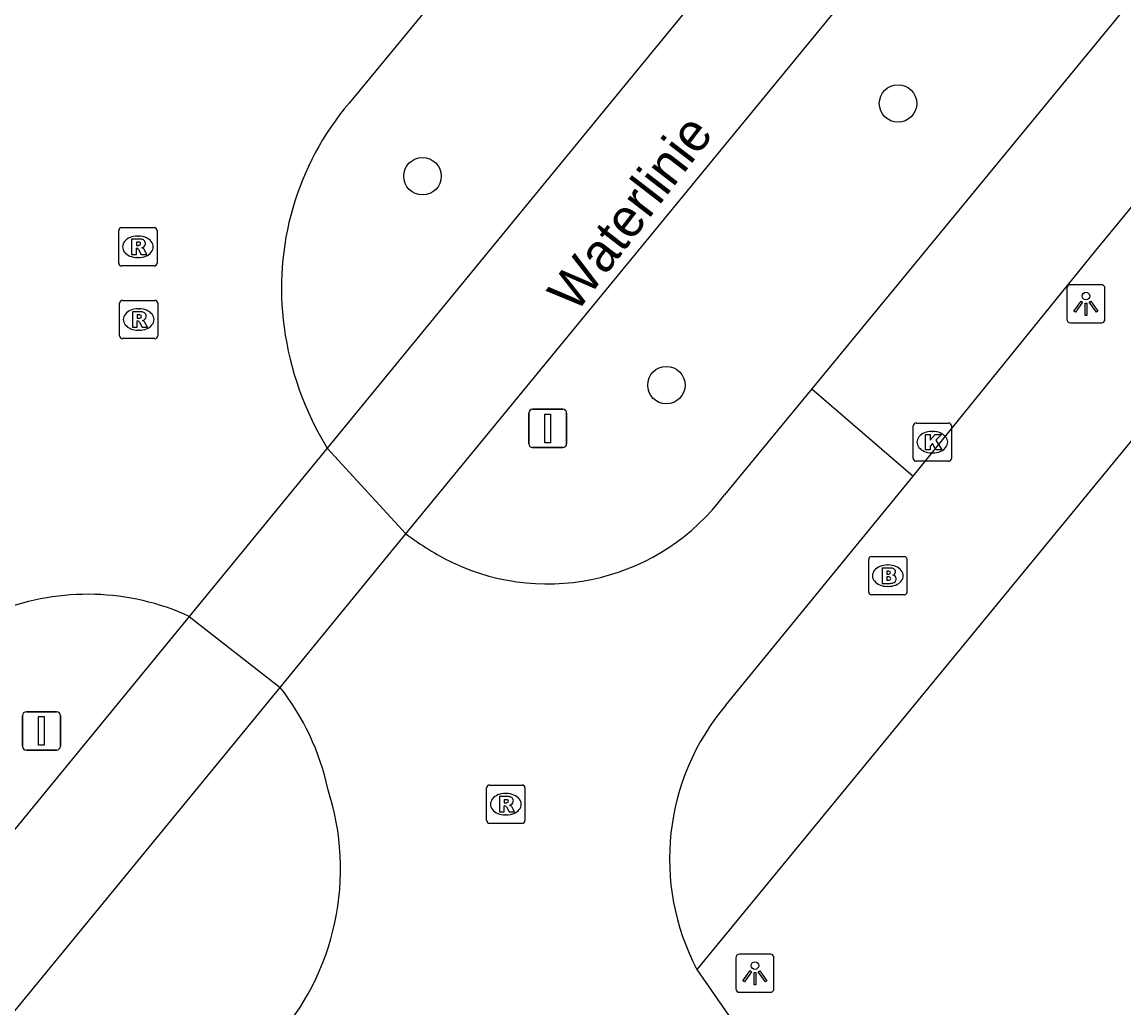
# Model space of a CAD drawing. Extents: x 155275 to 156263, y 382654 to 383635.
# Drawn here: x 155568.42 to 155597.21, y 382967.18 to 382992.94 of the extents above; entities that cross this region are included whole.
import ezdxf

# ---------------------------------------------------------------- set-up
doc = ezdxf.new("R2010")
doc.units = 0
for name, color, linetype in [('IMGEO_Boom', 7, 'Continuous'), ('IMGEO_Brandkraan', 7, 'Continuous'), ('IMGEO_Fietspad_gesloten', 7, 'Continuous'), ('IMGEO_Kolk', 7, 'Continuous'), ('IMGEO_Lichtpunt', 7, 'Continuous'), ('IMGEO_Openbare_ruimte_label', 7, 'Continuous'), ('IMGEO_Rijbaan_lokaal_gesloten', 7, 'Continuous'), ('IMGEO_Rijbaan_lokaal_open', 7, 'Continuous'), ('IMGEO_Rioolput', 7, 'Continuous'), ('IMGEO_Verkeersbordpaal', 7, 'Continuous'), ('IMGEO_Voetpad_open', 7, 'Continuous')]:
    doc.layers.add(name, color=color, linetype=linetype)

msp = doc.modelspace()

# ---------------------------------------------------------------- linework, layer by layer
at = {"layer": 'IMGEO_Boom'}
for centre in [(155591.307, 382990.81), (155578.883, 382988.909), (155585.255, 382983.451)]:
    msp.add_circle(centre, 0.489, dxfattribs=at)
at = {"layer": 'IMGEO_Brandkraan'}
for p, q in [((155590.54, 382978.046), (155590.54, 382978.898)), ((155590.615, 382978.972), (155591.467, 382978.972)), ((155591.028, 382978.752), (155591.053, 382978.752)), ((155591.541, 382978.898), (155591.541, 382978.046)), ((155591.051, 382978.192), (155591.026, 382978.192)), ((155591.467, 382977.972), (155590.615, 382977.972))]:
    msp.add_line(p, q, dxfattribs=at)
for points in [[(155590.54, 382978.046), (155590.54, 382978.898)], [(155590.615, 382978.972), (155591.467, 382978.972)], [(155591.541, 382978.898), (155591.541, 382978.046)], [(155590.888, 382978.672), (155590.888, 382978.272), (155591.101, 382978.272)], [(155591.119, 382978.672), (155590.888, 382978.672)], [(155591.067, 382978.591), (155591.013, 382978.591), (155591.013, 382978.515)], [(155591.013, 382978.515), (155591.066, 382978.515)], [(155591.075, 382978.439), (155591.013, 382978.439), (155591.013, 382978.358)], [(155591.013, 382978.358), (155591.075, 382978.358)], [(155591.467, 382977.972), (155590.615, 382977.972)]]:
    msp.add_lwpolyline(points, dxfattribs=at)
for centre, radius, start, end in [((155590.617, 382978.896), 0.0765, 91.552, 178.448), ((155590.617, 382978.896), 0.0765, 91.552, 178.448), ((155591.465, 382978.896), 0.0765, 1.552, 88.448), ((155591.465, 382978.896), 0.0765, 1.552, 88.448), ((155591.068, 382978.553), 0.0379, 267.8285, 90.9355), ((155591.076, 382978.398), 0.0404, 269.8759, 90.5077), ((155591.123, 382978.527), 0.145, 59.4692, 91.5367), ((155591.148, 382978.574), 0.0922, 285.5137, 58.1501), ((155591.153, 382978.382), 0.105, 301.3115, 78.989), ((155591.107, 382978.523), 0.251, 268.6676, 293.5347), ((155590.617, 382978.048), 0.0765, 181.552, 268.448), ((155590.617, 382978.048), 0.0765, 181.552, 268.448), ((155591.465, 382978.048), 0.0765, 271.552, 358.448), ((155591.465, 382978.048), 0.0765, 271.552, 358.448)]:
    msp.add_arc(centre, radius, start, end, dxfattribs=at)
for centre, major_axis, ratio, start_param, end_param in [((155591.027, 382978.472), (-0.387, 0.002), 0.722429, 4.712389, 7.853982), ((155591.052, 382978.472), (-0.39, 0.002), 0.717154, 1.570796, 4.712389)]:
    msp.add_ellipse(centre, major_axis=major_axis, ratio=ratio, start_param=start_param, end_param=end_param, dxfattribs=at)
at = {"layer": 'IMGEO_Fietspad_gesloten'}
for points in [[(155706.581, 383139.306), (155702.643, 383134.878), (155693.747, 383124.076), (155661.118, 383084.828), (155644.459, 383064.506), (155599.926, 383010.505), (155576.394, 382981.806)], [(155578.449, 382979.563), (155602.123, 383008.412), (155669.504, 383090.181), (155696.136, 383122.234), (155702.244, 383129.715), (155705.062, 383133.055), (155708.331, 383136.749)], [(155578.449, 382979.563), (155576.394, 382981.806)], [(155572.789, 382977.41), (155548.966, 382948.356), (155528.673, 382923.729), (155507.607, 382898.405), (155494.374, 382882.291)], [(155572.789, 382977.41), (155575.161, 382975.555)], [(155496.67, 382880.437), (155497.335, 382881.332), (155511.334, 382898.215), (155518.802, 382907.088), (155545.301, 382939.168), (155575.161, 382975.555)]]:
    msp.add_lwpolyline(points, dxfattribs=at)
at = {"layer": 'IMGEO_Kolk'}
for p, q in [((155591.777, 382982.461), (155592.629, 382982.461)), ((155591.702, 382981.535), (155591.702, 382982.387)), ((155592.19, 382982.241), (155592.215, 382982.241)), ((155592.703, 382982.387), (155592.703, 382981.535)), ((155592.213, 382981.681), (155592.188, 382981.681)), ((155592.629, 382981.461), (155591.777, 382981.461))]:
    msp.add_line(p, q, dxfattribs=at)
for points in [[(155591.777, 382982.461), (155592.629, 382982.461)], [(155591.702, 382981.535), (155591.702, 382982.387)], [(155592.023, 382982.161), (155592.146, 382982.161), (155592.146, 382982.01), (155592.276, 382982.161), (155592.44, 382982.161), (155592.294, 382982.01), (155592.447, 382981.761), (155592.295, 382981.761), (155592.21, 382981.925), (155592.146, 382981.858), (155592.146, 382981.761), (155592.023, 382981.761), (155592.023, 382982.161)], [(155592.703, 382982.387), (155592.703, 382981.535)], [(155592.629, 382981.461), (155591.777, 382981.461)]]:
    msp.add_lwpolyline(points, dxfattribs=at)
for centre, start, end in [((155591.779, 382982.385), 91.552, 178.448), ((155591.779, 382982.385), 91.552, 178.448), ((155592.627, 382982.385), 1.552, 88.448), ((155592.627, 382982.385), 1.552, 88.448), ((155591.779, 382981.537), 181.552, 268.448), ((155591.779, 382981.537), 181.552, 268.448), ((155592.627, 382981.537), 271.552, 358.448), ((155592.627, 382981.537), 271.552, 358.448)]:
    msp.add_arc(centre, 0.0765, start, end, dxfattribs=at)
for centre, major_axis, ratio, start_param, end_param in [((155592.189, 382981.961), (-0.387, 0.002), 0.722429, 4.712389, 7.853982), ((155592.214, 382981.961), (-0.39, 0.002), 0.717154, 1.570796, 4.712389)]:
    msp.add_ellipse(centre, major_axis=major_axis, ratio=ratio, start_param=start_param, end_param=end_param, dxfattribs=at)
at = {"layer": 'IMGEO_Lichtpunt'}
for p, q in [((155595.717, 382985.98), (155595.717, 382985.173)), ((155595.717, 382985.98), (155595.717, 382985.173)), ((155596.619, 382986.075), (155595.811, 382986.075)), ((155596.619, 382986.075), (155595.811, 382986.075)), ((155596.713, 382985.173), (155596.713, 382985.98)), ((155596.713, 382985.173), (155596.713, 382985.98)), ((155595.811, 382985.079), (155596.619, 382985.079)), ((155595.811, 382985.079), (155596.619, 382985.079)), ((155587.069, 382968.489), (155587.069, 382967.682)), ((155587.069, 382968.489), (155587.069, 382967.682)), ((155587.971, 382968.584), (155587.163, 382968.584)), ((155587.971, 382968.584), (155587.163, 382968.584)), ((155588.065, 382967.682), (155588.065, 382968.489)), ((155588.065, 382967.682), (155588.065, 382968.489)), ((155587.163, 382967.588), (155587.971, 382967.588)), ((155587.163, 382967.588), (155587.971, 382967.588))]:
    msp.add_line(p, q, dxfattribs=at)
for points in [[(155596.091, 382985.644), (155596.13, 382985.616), (155595.942, 382985.354), (155595.904, 382985.381), (155596.091, 382985.644)], [(155596.303, 382985.616), (155596.341, 382985.643), (155596.528, 382985.381), (155596.489, 382985.353), (155596.303, 382985.616)], [(155596.193, 382985.596), (155596.24, 382985.596), (155596.24, 382985.274), (155596.193, 382985.274), (155596.193, 382985.596)], [(155587.443, 382968.153), (155587.482, 382968.125), (155587.294, 382967.863), (155587.256, 382967.89), (155587.443, 382968.153)], [(155587.545, 382968.105), (155587.592, 382968.105), (155587.592, 382967.783), (155587.545, 382967.783), (155587.545, 382968.105)], [(155587.655, 382968.125), (155587.693, 382968.152), (155587.88, 382967.89), (155587.841, 382967.862), (155587.655, 382968.125)]]:
    msp.add_lwpolyline(points, dxfattribs=at)
for centre in [(155596.216, 382985.778), (155587.568, 382968.287)]:
    msp.add_circle(centre, 0.0994, dxfattribs=at)
for centre, start, end in [((155595.811, 382985.98), 90, 180), ((155595.811, 382985.98), 90, 180), ((155596.619, 382985.98), 0, 90), ((155596.619, 382985.98), 0, 90), ((155595.811, 382985.173), 180, 270), ((155595.811, 382985.173), 180, 270), ((155596.619, 382985.173), 270, 0), ((155596.619, 382985.173), 270, 360), ((155587.163, 382968.489), 90, 180), ((155587.163, 382968.489), 90, 180), ((155587.971, 382968.489), 0, 90), ((155587.971, 382968.489), 0, 90), ((155587.163, 382967.682), 180, 270), ((155587.163, 382967.682), 180, 270), ((155587.971, 382967.682), 270, 0), ((155587.971, 382967.682), 270, 360)]:
    msp.add_arc(centre, 0.0946, start, end, dxfattribs=at)
at = {"layer": 'IMGEO_Rijbaan_lokaal_gesloten'}
for points in [[(155711.442, 383132.126), (155679.74, 383093.59), (155589.051, 382983.35)], [(155591.698, 382981.075), (155596.474, 382986.965), (155631.252, 383029.213), (155635.105, 383033.893), (155643.042, 383043.534), (155646.823, 383048.128), (155682.427, 383091.379), (155708.323, 383122.836)]]:
    msp.add_lwpolyline(points, dxfattribs=at)
at = {"layer": 'IMGEO_Rijbaan_lokaal_open'}
for points in [[(155580.772, 382995.445), (155576.965, 382990.82)], [(155589.051, 382983.35), (155586.774, 382980.583)], [(155589.051, 382983.35), (155591.698, 382981.075)], [(155576.394, 382981.806), (155572.789, 382977.41)], [(155586.805, 382975.087), (155591.698, 382981.075)], [(155575.161, 382975.555), (155578.449, 382979.563)], [(155586.051, 382968.185), (155586.875, 382966.986), (155588.307, 382964.774)]]:
    msp.add_lwpolyline(points, dxfattribs=at)
for centre, radius, start, end in [((155582.679, 382985.99), 7.482, 139.7934, 187.8847), ((155583.26, 382986.034), 8.064, 187.6253, 211.6226), ((155582.142, 382984.034), 5.776, 244.5799, 323.3144), ((155583.212, 382985.954), 7.971, 233.3012, 243.5575), ((155570.132, 382971.569), 6.417, 65.5437, 111.1126), ((155570.121, 382971.567), 6.427, 12.0274, 38.354), ((155591.55, 382971.076), 6.213, 139.7949, 207.7361), ((155570.032, 382970.816), 6.709, 317.6614, 18.1527)]:
    msp.add_arc(centre, radius, start, end, dxfattribs=at)
at = {"layer": 'IMGEO_Rioolput'}
for p, q in [((155570.946, 382986.639), (155570.946, 382987.491)), ((155571.021, 382987.565), (155571.873, 382987.565)), ((155571.434, 382987.345), (155571.459, 382987.345)), ((155571.947, 382987.491), (155571.947, 382986.639)), ((155571.457, 382986.785), (155571.432, 382986.785)), ((155571.873, 382986.565), (155571.021, 382986.565)), ((155571.041, 382985.665), (155571.893, 382985.665)), ((155570.966, 382984.739), (155570.966, 382985.591)), ((155571.454, 382985.445), (155571.479, 382985.445)), ((155571.967, 382985.591), (155571.967, 382984.739)), ((155571.477, 382984.885), (155571.452, 382984.885)), ((155571.893, 382984.665), (155571.041, 382984.665)), ((155580.634, 382973.001), (155581.486, 382973.001)), ((155580.559, 382972.075), (155580.559, 382972.927)), ((155581.047, 382972.781), (155581.072, 382972.781)), ((155581.56, 382972.927), (155581.56, 382972.075)), ((155581.07, 382972.221), (155581.045, 382972.221)), ((155581.486, 382972.001), (155580.634, 382972.001))]:
    msp.add_line(p, q, dxfattribs=at)
for points in [[(155570.946, 382986.639), (155570.946, 382987.491)], [(155571.021, 382987.565), (155571.873, 382987.565)], [(155571.947, 382987.491), (155571.947, 382986.639)], [(155571.535, 382987.263), (155571.283, 382987.265), (155571.283, 382986.865)], [(155571.461, 382987.184), (155571.407, 382987.184), (155571.407, 382987.103)], [(155571.407, 382987.103), (155571.459, 382987.103)], [(155571.283, 382986.865), (155571.407, 382986.865), (155571.407, 382987.027), (155571.418, 382987.027)], [(155571.465, 382986.998), (155571.536, 382986.865), (155571.676, 382986.865), (155571.611, 382986.991)], [(155571.873, 382986.565), (155571.021, 382986.565)], [(155571.041, 382985.665), (155571.893, 382985.665)], [(155570.966, 382984.739), (155570.966, 382985.591)], [(155571.555, 382985.363), (155571.303, 382985.365), (155571.303, 382984.965)], [(155571.967, 382985.591), (155571.967, 382984.739)], [(155571.303, 382984.965), (155571.427, 382984.965), (155571.427, 382985.127), (155571.438, 382985.127)], [(155571.481, 382985.284), (155571.427, 382985.284), (155571.427, 382985.203)], [(155571.427, 382985.203), (155571.479, 382985.203)], [(155571.485, 382985.098), (155571.556, 382984.965), (155571.696, 382984.965), (155571.631, 382985.091)], [(155571.893, 382984.665), (155571.041, 382984.665)], [(155580.634, 382973.001), (155581.486, 382973.001)], [(155580.559, 382972.075), (155580.559, 382972.927)], [(155581.148, 382972.699), (155580.896, 382972.701), (155580.896, 382972.301)], [(155581.56, 382972.927), (155581.56, 382972.075)], [(155580.896, 382972.301), (155581.02, 382972.301), (155581.02, 382972.463), (155581.031, 382972.463)], [(155581.074, 382972.62), (155581.02, 382972.62), (155581.02, 382972.539)], [(155581.02, 382972.539), (155581.072, 382972.539)], [(155581.078, 382972.434), (155581.149, 382972.301), (155581.289, 382972.301), (155581.224, 382972.427)], [(155581.486, 382972.001), (155580.634, 382972.001)]]:
    msp.add_lwpolyline(points, dxfattribs=at)
for centre, radius, start, end in [((155571.023, 382987.489), 0.0765, 91.552, 178.448), ((155571.023, 382987.489), 0.0765, 91.552, 178.448), ((155571.871, 382987.489), 0.0765, 1.552, 88.448), ((155571.871, 382987.489), 0.0765, 1.552, 88.448), ((155571.443, 382987.292), 0.19, 274.7715, 282.9687), ((155571.467, 382987.088), 0.0964, 77.0061, 93.1865), ((155571.481, 382987.145), 0.0378, 276.6634, 79.6772), ((155571.534, 382987.153), 0.109, 350.3612, 89.416), ((155571.532, 382987.153), 0.112, 277.5842, 350.9817), ((155571.417, 382986.974), 0.0533, 26.0293, 88.6989), ((155571.516, 382986.938), 0.108, 29.5134, 73.7905), ((155571.023, 382986.641), 0.0765, 181.552, 268.448), ((155571.023, 382986.641), 0.0765, 181.552, 268.448), ((155571.871, 382986.641), 0.0765, 271.552, 358.448), ((155571.871, 382986.641), 0.0765, 271.552, 358.448), ((155571.043, 382985.589), 0.0765, 91.552, 178.448), ((155571.043, 382985.589), 0.0765, 91.552, 178.448), ((155571.891, 382985.589), 0.0765, 1.552, 88.448), ((155571.891, 382985.589), 0.0765, 1.552, 88.448), ((155571.554, 382985.253), 0.109, 350.3612, 89.416), ((155571.437, 382985.074), 0.0533, 26.0293, 88.6989), ((155571.463, 382985.392), 0.19, 274.7715, 282.9687), ((155571.487, 382985.188), 0.0964, 77.0061, 93.1865), ((155571.501, 382985.245), 0.0378, 276.6634, 79.6772), ((155571.552, 382985.253), 0.112, 277.5842, 350.9817), ((155571.536, 382985.038), 0.108, 29.5134, 73.7905), ((155571.043, 382984.741), 0.0765, 181.552, 268.448), ((155571.043, 382984.741), 0.0765, 181.552, 268.448), ((155571.891, 382984.741), 0.0765, 271.552, 358.448), ((155571.891, 382984.741), 0.0765, 271.552, 358.448), ((155580.636, 382972.925), 0.0765, 91.552, 178.448), ((155580.636, 382972.925), 0.0765, 91.552, 178.448), ((155581.484, 382972.925), 0.0765, 1.552, 88.448), ((155581.484, 382972.925), 0.0765, 1.552, 88.448), ((155581.147, 382972.589), 0.109, 350.3612, 89.416), ((155581.03, 382972.41), 0.0533, 26.0293, 88.6989), ((155581.056, 382972.728), 0.19, 274.7715, 282.9687), ((155581.08, 382972.524), 0.0964, 77.0061, 93.1865), ((155581.094, 382972.581), 0.0378, 276.6634, 79.6772), ((155581.145, 382972.589), 0.112, 277.5842, 350.9817), ((155581.129, 382972.374), 0.108, 29.5134, 73.7905), ((155580.636, 382972.077), 0.0765, 181.552, 268.448), ((155580.636, 382972.077), 0.0765, 181.552, 268.448), ((155581.484, 382972.077), 0.0765, 271.552, 358.448), ((155581.484, 382972.077), 0.0765, 271.552, 358.448)]:
    msp.add_arc(centre, radius, start, end, dxfattribs=at)
for centre, major_axis, ratio, start_param, end_param in [((155571.433, 382987.065), (-0.387, 0.002), 0.722429, 4.712389, 7.853982), ((155571.458, 382987.065), (-0.39, 0.002), 0.717154, 1.570796, 4.712389), ((155571.453, 382985.165), (-0.387, 0.002), 0.722429, 4.712389, 7.853982), ((155571.478, 382985.165), (-0.39, 0.002), 0.717154, 1.570796, 4.712389), ((155581.046, 382972.501), (-0.387, 0.002), 0.722429, 4.712389, 7.853982), ((155581.071, 382972.501), (-0.39, 0.002), 0.717154, 1.570796, 4.712389)]:
    msp.add_ellipse(centre, major_axis=major_axis, ratio=ratio, start_param=start_param, end_param=end_param, dxfattribs=at)
at = {"layer": 'IMGEO_Verkeersbordpaal'}
for p, q in [((155581.759, 382982.819), (155582.549, 382982.819)), ((155582.549, 382982.819), (155581.759, 382982.819)), ((155581.659, 382981.919), (155581.659, 382982.719)), ((155581.659, 382982.719), (155581.659, 382981.919)), ((155582.649, 382982.719), (155582.649, 382981.919)), ((155582.649, 382981.919), (155582.649, 382982.719)), ((155582.549, 382981.819), (155581.759, 382981.819)), ((155581.759, 382981.819), (155582.549, 382981.819)), ((155568.432, 382974.017), (155568.432, 382974.817)), ((155568.432, 382974.817), (155568.432, 382974.017)), ((155568.532, 382974.917), (155569.322, 382974.917)), ((155569.322, 382974.917), (155568.532, 382974.917)), ((155569.422, 382974.817), (155569.422, 382974.017)), ((155569.422, 382974.017), (155569.422, 382974.817)), ((155569.322, 382973.917), (155568.532, 382973.917)), ((155568.532, 382973.917), (155569.322, 382973.917))]:
    msp.add_line(p, q, dxfattribs=at)
for points in [[(155582.079, 382982.694), (155582.229, 382982.694), (155582.229, 382981.944), (155582.079, 382981.944), (155582.079, 382982.694)], [(155568.852, 382974.792), (155569.002, 382974.792), (155569.002, 382974.042), (155568.852, 382974.042), (155568.852, 382974.792)]]:
    msp.add_lwpolyline(points, dxfattribs=at)
for centre, start, end in [((155581.759, 382982.719), 90, 180), ((155581.759, 382982.719), 90, 180), ((155582.549, 382982.719), 0, 90), ((155582.549, 382982.719), 360, 90), ((155581.759, 382981.919), 180, 270), ((155581.759, 382981.919), 180, 270), ((155582.549, 382981.919), 270, 0), ((155582.549, 382981.919), 270, 0), ((155568.532, 382974.817), 90, 180), ((155568.532, 382974.817), 90, 180), ((155569.322, 382974.817), 0, 90), ((155569.322, 382974.817), 360, 90), ((155568.532, 382974.017), 180, 270), ((155568.532, 382974.017), 180, 270), ((155569.322, 382974.017), 270, 0), ((155569.322, 382974.017), 270, 0)]:
    msp.add_arc(centre, 0.1, start, end, dxfattribs=at)
at = {"layer": 'IMGEO_Voetpad_open'}
msp.add_lwpolyline([(155599.543, 382984.601), (155586.051, 382968.185)], dxfattribs=at)

# ---------------------------------------------------------------- texts
at = {"layer": 'IMGEO_Openbare_ruimte_label'}
msp.add_text('Waterlinie', height=1, rotation=52.3965, dxfattribs=at).set_placement((155582.885, 382985.301))
msp.add_text('Waterlinie', height=1, rotation=52.3965, dxfattribs=at).set_placement((155582.885, 382985.301))

doc.saveas('drawing.dxf')
